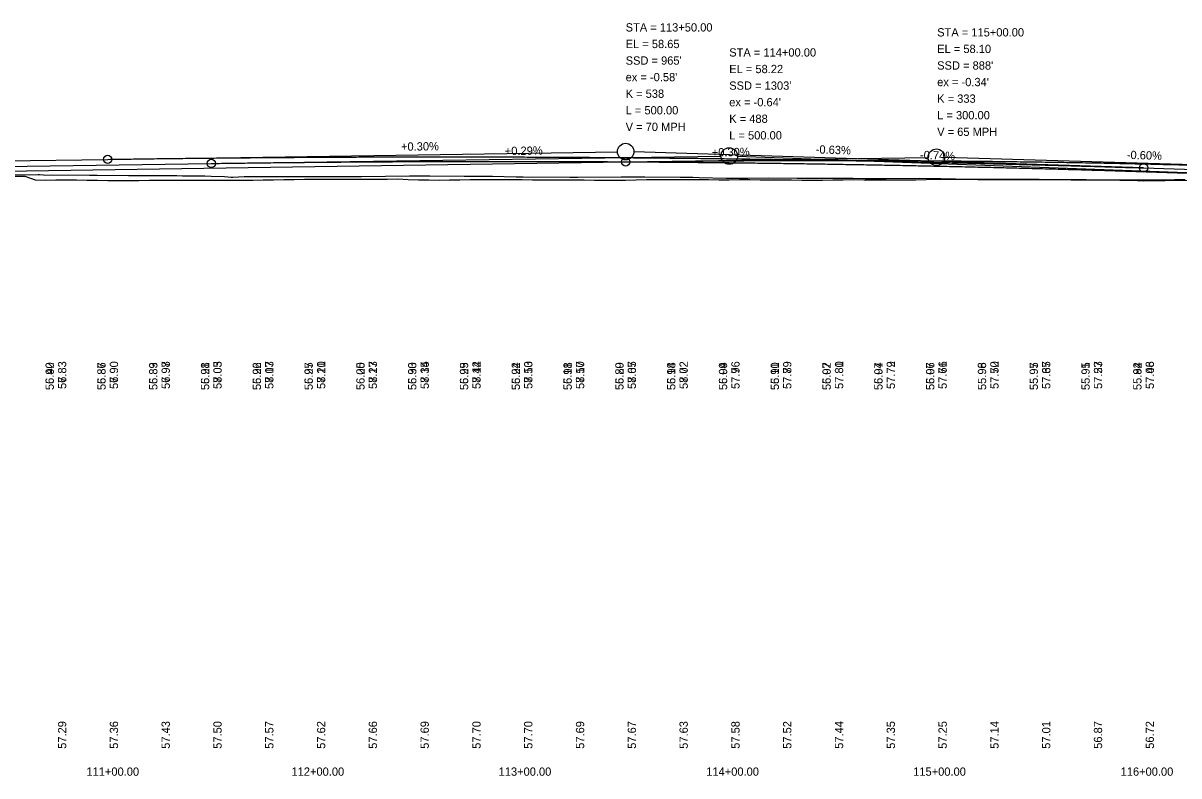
# Model space of a CAD drawing. Extents: x 3880794 to 3915434, y 287517 to 300173.
# Drawn here: x 3891597 to 3892155, y 296520 to 296883 of the extents above; entities that cross this region are included whole.
import ezdxf

# ---------------------------------------------------------------- set-up
doc = ezdxf.new("R2010")
doc.units = 0
for name, color, linetype in [('Level 1', 7, 'Continuous'), ('Level 2', 7, 'Continuous'), ('Level 30', 7, 'Continuous'), ('Level 31', 7, 'Continuous'), ('Level 32', 7, 'Continuous')]:
    doc.layers.add(name, color=color, linetype=linetype)

msp = doc.modelspace()

# ---------------------------------------------------------------- linework, layer by layer
at = {"layer": 'Level 1'}
for p, q in [((3891588.3, 296816.51), (3891638.3, 296817.26)), ((3891638.3, 296817.26), (3891884.3, 296820.95)), ((3891688.3, 296815.27), (3891934.3, 296818.8)), ((3892138.3, 296813.13), (3891892.3, 296820.88)), ((3892188.3, 296809.63), (3891942.29, 296818.71)), ((3891588.3, 296813.84), (3891688.3, 296815.27)), ((3892138.3, 296813.13), (3892188.3, 296811.56))]:
    msp.add_line(p, q, dxfattribs=at)
for points in [[(3891581.65, 296809.97), (3891600.37, 296809.86), (3891604.7, 296809.89), (3891605.35, 296809.88), (3891607.32, 296809.81), (3891629.58, 296809.63), (3891631.31, 296809.58), (3891633.14, 296809.55), (3891648.3, 296809.52), (3891649.99, 296809.48), (3891652.62, 296809.39), (3891671.74, 296809.39), (3891674.39, 296809.38), (3891685.2, 296809.27), (3891688.29, 296809.16), (3891694.76, 296808.97), (3891697.95, 296808.68), (3891698.68, 296808.69), (3891704.24, 296809.06), (3891705.15, 296809.06), (3891705.58, 296809.06), (3891712.33, 296809.05), (3891727.04, 296808.96), (3891728.62, 296808.94), (3891744.29, 296809.05), (3891752.67, 296809.04), (3891758.4, 296809.03), (3891760.76, 296809), (3891783.92, 296809.23), (3891784.67, 296809.23), (3891786.21, 296809.24), (3891793.8, 296809.27), (3891810.44, 296809.2), (3891810.78, 296809.19), (3891812.7, 296809.18), (3891813.11, 296809.18), (3891824.1, 296809.09), (3891835.39, 296808.87), (3891836.75, 296808.87), (3891838.85, 296808.87), (3891861.34, 296808.7), (3891862.59, 296808.69), (3891865.27, 296808.65), (3891886.15, 296808.77), (3891888.37, 296808.77), (3891894.43, 296808.76), (3891897.64, 296808.8), (3891914.61, 296808.65), (3891920.76, 296808.59), (3891923.81, 296808.56), (3891936.78, 296808.18), (3891947.35, 296808.19), (3891957.3, 296808.32), (3891971.1, 296808.16), (3891975.48, 296808.11), (3891981.2, 296808.1), (3891998.12, 296808.11), (3892003.94, 296808), (3892005.69, 296808), (3892013.98, 296808.09), (3892030.33, 296808.17), (3892040.44, 296808), (3892054.62, 296807.7), (3892056.89, 296807.65), (3892062.7, 296807.65), (3892078.69, 296807.69)], [(3892078.69, 296807.69), (3892086.3, 296807.63), (3892087.86, 296807.63), (3892094.52, 296807.59), (3892110.57, 296807.52), (3892118.26, 296807.44), (3892135.32, 296807.04), (3892138.13, 296806.96), (3892159.56, 296807.2)]]:
    msp.add_lwpolyline(points, dxfattribs=at)
for centre in [(3891888.3, 296821.01), (3891938.3, 296818.86)]:
    msp.add_circle(centre, 4, dxfattribs=at)
for points in [[(3891638.3, 296817.26), (3891648.3, 296817.4), (3891658.3, 296817.54), (3891668.3, 296817.67), (3891678.3, 296817.78), (3891688.3, 296817.89), (3891698.3, 296817.99), (3891708.3, 296818.08), (3891718.3, 296818.16), (3891728.3, 296818.23), (3891738.3, 296818.29), (3891748.3, 296818.34), (3891758.3, 296818.39), (3891768.3, 296818.42), (3891778.3, 296818.45), (3891788.3, 296818.46), (3891798.3, 296818.47), (3891808.3, 296818.46), (3891818.3, 296818.45), (3891828.3, 296818.43), (3891838.3, 296818.4), (3891848.3, 296818.36), (3891858.3, 296818.31), (3891868.3, 296818.25), (3891878.3, 296818.18), (3891888.3, 296818.1), (3891898.3, 296818.01), (3891908.3, 296817.92), (3891918.3, 296817.81), (3891928.3, 296817.7), (3891938.3, 296817.57), (3891948.3, 296817.44), (3891958.3, 296817.3), (3891968.3, 296817.14), (3891978.3, 296816.98), (3891988.3, 296816.81), (3891998.3, 296816.63), (3892008.3, 296816.44), (3892018.3, 296816.24), (3892028.3, 296816.03), (3892038.3, 296815.82), (3892048.3, 296815.59), (3892058.3, 296815.35), (3892068.3, 296815.11), (3892078.3, 296814.85), (3892088.3, 296814.59), (3892098.3, 296814.32), (3892108.3, 296814.04), (3892118.3, 296813.74), (3892128.3, 296813.44), (3892138.3, 296813.13)], [(3891688.3, 296815.27), (3891698.3, 296815.41), (3891708.3, 296815.54), (3891718.3, 296815.66), (3891728.3, 296815.77), (3891738.3, 296815.86), (3891748.3, 296815.95), (3891758.3, 296816.03), (3891768.3, 296816.09), (3891778.3, 296816.15), (3891788.3, 296816.19), (3891798.3, 296816.23), (3891808.3, 296816.26), (3891818.3, 296816.27), (3891828.3, 296816.28), (3891838.3, 296816.27), (3891848.3, 296816.26), (3891858.3, 296816.23), (3891868.3, 296816.19), (3891878.3, 296816.15), (3891888.3, 296816.09), (3891898.3, 296816.02), (3891908.3, 296815.95), (3891918.3, 296815.86), (3891928.3, 296815.76), (3891938.3, 296815.66), (3891948.3, 296815.54), (3891958.3, 296815.41), (3891968.3, 296815.27), (3891978.3, 296815.12), (3891988.3, 296814.96), (3891998.3, 296814.79), (3892008.3, 296814.62), (3892018.3, 296814.43), (3892028.3, 296814.23), (3892038.3, 296814.02), (3892048.3, 296813.8), (3892058.3, 296813.56), (3892068.3, 296813.32), (3892078.3, 296813.07), (3892088.3, 296812.81), (3892098.3, 296812.54), (3892108.3, 296812.26), (3892118.3, 296811.97), (3892128.3, 296811.66), (3892138.3, 296811.35), (3892148.3, 296811.03), (3892158.3, 296810.7), (3892168.3, 296810.35), (3892178.3, 296810), (3892188.3, 296809.63)]]:
    msp.add_spline(points, degree=3, dxfattribs=at)
at = {"layer": 'Level 2'}
for p, q in [((3891588.3, 296811.51), (3891888.3, 296816.01)), ((3891888.3, 296816.01), (3892034.3, 296818.2)), ((3892188.3, 296813.76), (3892042.3, 296818.14))]:
    msp.add_line(p, q, dxfattribs=at)
for points in [[(3891593.3, 296809.08), (3891598.3, 296809.2), (3891603.3, 296807.3), (3891608.3, 296807.29), (3891613.3, 296807.34), (3891618.3, 296807.36), (3891623.3, 296807.31), (3891628.3, 296807.25), (3891633.3, 296807.18), (3891638.3, 296807.1), (3891643.3, 296807.05), (3891648.3, 296807.08), (3891653.3, 296807.13), (3891658.3, 296807.18), (3891663.3, 296807.19), (3891668.3, 296807.2), (3891673.3, 296807.2), (3891678.3, 296807.19), (3891683.3, 296807.25), (3891688.3, 296807.29), (3891693.3, 296807.26), (3891698.3, 296807.23), (3891703.3, 296807.25), (3891708.3, 296807.26), (3891713.3, 296807.34), (3891718.3, 296807.4), (3891723.3, 296807.47), (3891728.3, 296807.55), (3891733.3, 296807.64), (3891738.3, 296807.63), (3891743.3, 296807.64), (3891748.3, 296807.7), (3891753.3, 296807.76), (3891758.3, 296807.75), (3891763.3, 296807.75), (3891768.3, 296807.67), (3891773.3, 296807.77), (3891778.3, 296807.78), (3891783.3, 296807.57), (3891788.3, 296807.39), (3891793.3, 296807.3), (3891798.3, 296807.23), (3891803.3, 296807.32), (3891808.3, 296807.43), (3891813.3, 296807.52), (3891818.3, 296807.52), (3891823.3, 296807.52), (3891828.3, 296807.5), (3891833.3, 296807.48), (3891838.3, 296807.46), (3891843.3, 296807.43), (3891848.3, 296807.39), (3891853.3, 296807.37), (3891858.3, 296807.36), (3891863.3, 296807.32), (3891868.3, 296807.3), (3891873.3, 296807.27), (3891878.3, 296807.24), (3891883.3, 296807.19), (3891888.3, 296807.21), (3891893.3, 296807.34), (3891898.3, 296807.46), (3891903.3, 296807.49), (3891908.3, 296807.48), (3891913.3, 296807.48), (3891918.3, 296807.53), (3891923.3, 296807.58), (3891928.3, 296807.5), (3891933.3, 296807.41), (3891938.3, 296807.43), (3891943.3, 296807.49), (3891948.3, 296807.46), (3891953.3, 296807.39), (3891958.3, 296807.32), (3891963.3, 296807.31), (3891968.3, 296807.31), (3891973.3, 296807.29), (3891978.3, 296807.25), (3891983.3, 296807.24), (3891988.3, 296807.35), (3891993.3, 296807.45), (3891998.3, 296807.48), (3892003.3, 296807.43), (3892008.3, 296807.43), (3892013.3, 296807.44), (3892018.3, 296807.45), (3892023.3, 296807.44), (3892028.3, 296807.43), (3892033.3, 296807.48), (3892038.3, 296807.62)], [(3892038.3, 296807.62), (3892043.3, 296807.75), (3892048.3, 296807.76), (3892053.3, 296807.68), (3892058.3, 296807.59), (3892063.3, 296807.55), (3892068.3, 296807.53), (3892073.3, 296807.51), (3892078.3, 296807.48), (3892083.3, 296807.48), (3892088.3, 296807.53), (3892093.3, 296807.58), (3892098.3, 296807.49), (3892103.3, 296807.37), (3892108.3, 296807.33), (3892113.3, 296807.33), (3892118.3, 296807.33), (3892123.3, 296807.32), (3892128.3, 296807.31), (3892133.3, 296807.34), (3892138.3, 296807.38), (3892143.3, 296807.42), (3892148.3, 296807.45), (3892153.3, 296807.47), (3892158.3, 296807.46)]]:
    msp.add_lwpolyline(points, dxfattribs=at)
for centre, radius in [((3892038.3, 296818.26), 4), ((3891888.3, 296816.01), 2)]:
    msp.add_circle(centre, radius, dxfattribs=at)
msp.add_spline([(3891888.3, 296816.01), (3891894.3, 296816.09), (3891900.3, 296816.18), (3891906.3, 296816.25), (3891912.3, 296816.32), (3891918.3, 296816.39), (3891924.3, 296816.45), (3891930.3, 296816.5), (3891936.3, 296816.55), (3891942.3, 296816.6), (3891948.3, 296816.64), (3891954.3, 296816.67), (3891960.3, 296816.7), (3891966.3, 296816.72), (3891972.3, 296816.74), (3891978.3, 296816.75), (3891984.3, 296816.76), (3891990.3, 296816.76), (3891996.3, 296816.75), (3892002.3, 296816.74), (3892008.3, 296816.73), (3892014.3, 296816.71), (3892020.3, 296816.68), (3892026.3, 296816.65), (3892032.3, 296816.61), (3892038.3, 296816.57), (3892044.3, 296816.52), (3892050.3, 296816.47), (3892056.3, 296816.41), (3892062.3, 296816.35), (3892068.3, 296816.28), (3892074.3, 296816.2), (3892080.3, 296816.12), (3892086.3, 296816.04), (3892092.3, 296815.95), (3892098.3, 296815.85), (3892104.3, 296815.75), (3892110.3, 296815.64), (3892116.3, 296815.53), (3892122.3, 296815.41), (3892128.3, 296815.29), (3892134.3, 296815.16), (3892140.3, 296815.02), (3892146.3, 296814.88), (3892152.3, 296814.74), (3892158.3, 296814.59), (3892164.3, 296814.43), (3892170.3, 296814.27), (3892176.3, 296814.11), (3892182.3, 296813.93), (3892188.3, 296813.76)], degree=3, dxfattribs=at)
at = {"layer": 'Level 31'}
for centre in [(3891638.3, 296817.26), (3891688.3, 296815.27), (3892138.3, 296813.13)]:
    msp.add_circle(centre, 2, dxfattribs=at)

# ---------------------------------------------------------------- texts
at = {"layer": 'Level 2'}
for s, p in [('STA = 115+00.00', (3892038.67, 296876.57)), ('EL = 58.10', (3892038.67, 296868.57)), ("SSD = 888'", (3892038.67, 296860.57)), ("ex = -0.34'", (3892038.67, 296852.57)), ('K = 333', (3892038.67, 296844.57)), ('L = 300.00', (3892038.67, 296836.57)), ('V = 65 MPH', (3892038.67, 296828.57)), ('111+00.00', (3891628.03, 296519.76)), ('112+00.00', (3891727.02, 296519.76)), ('113+00.00', (3891826.99, 296519.76)), ('114+00.00', (3891927.21, 296519.76)), ('115+00.00', (3892027.09, 296519.76)), ('116+00.00', (3892127.21, 296519.76))]:
    msp.add_text(s, height=4, dxfattribs=at).set_placement(p)
for s, rotation, p in [('+0.30%', 0.8594, (3891929.9, 296818.63)), ('-0.60%', 358.2816, (3892130.16, 296817.5)), ('56.83', 90, (3891618.3, 296706.43)), ('56.90', 90, (3891643.3, 296706.43)), ('56.98', 90, (3891668.3, 296706.43)), ('57.05', 90, (3891693.3, 296706.43)), ('57.13', 90, (3891718.3, 296706.43)), ('57.20', 90, (3891743.3, 296706.43)), ('57.27', 90, (3891768.3, 296706.43)), ('57.35', 90, (3891793.3, 296706.43)), ('57.42', 90, (3891818.3, 296706.43)), ('57.50', 90, (3891843.3, 296706.43)), ('57.57', 90, (3891868.3, 296706.43)), ('57.65', 90, (3891893.3, 296706.43)), ('57.72', 90, (3891918.3, 296706.43)), ('57.76', 90, (3891943.3, 296706.43)), ('57.79', 90, (3891968.3, 296706.43)), ('57.80', 90, (3891993.3, 296706.43)), ('57.79', 90, (3892018.3, 296706.43)), ('57.76', 90, (3892043.3, 296706.43)), ('57.72', 90, (3892068.3, 296706.43)), ('57.65', 90, (3892093.3, 296706.43)), ('57.57', 90, (3892118.3, 296706.43)), ('57.46', 90, (3892143.3, 296706.43))]:
    msp.add_text(s, height=4, rotation=rotation, dxfattribs=at).set_placement(p)
at = {"layer": 'Level 30'}
for s, p in [('56.40', (3891612.3, 296705.91)), ('56.36', (3891637.3, 296705.91)), ('56.33', (3891662.3, 296705.91)), ('56.28', (3891687.3, 296705.91)), ('56.26', (3891712.3, 296705.91)), ('56.25', (3891737.3, 296705.91)), ('56.25', (3891762.3, 296705.91)), ('56.30', (3891787.3, 296705.91)), ('56.29', (3891812.3, 296705.91)), ('56.22', (3891837.3, 296705.91)), ('56.18', (3891862.3, 296705.91)), ('56.20', (3891887.3, 296705.91)), ('56.18', (3891912.3, 296705.91)), ('56.09', (3891937.3, 296705.91)), ('56.10', (3891962.3, 296705.91)), ('56.07', (3891987.3, 296705.91)), ('56.07', (3892012.3, 296705.91)), ('56.06', (3892037.3, 296705.91)), ('55.98', (3892062.3, 296705.91)), ('55.97', (3892087.3, 296705.91)), ('55.95', (3892112.3, 296705.91)), ('55.84', (3892137.3, 296705.91))]:
    msp.add_text(s, height=4, rotation=90, dxfattribs=at).set_placement(p)
for s, p in [('111+00.00', (3891628.03, 296519.76)), ('111+00.00', (3891628.03, 296519.76)), ('111+00.00', (3891628.03, 296519.76)), ('112+00.00', (3891727.02, 296519.76)), ('112+00.00', (3891727.02, 296519.76)), ('112+00.00', (3891727.02, 296519.76)), ('113+00.00', (3891826.99, 296519.76)), ('113+00.00', (3891826.99, 296519.76)), ('113+00.00', (3891826.99, 296519.76)), ('114+00.00', (3891927.21, 296519.76)), ('114+00.00', (3891927.21, 296519.76)), ('114+00.00', (3891927.21, 296519.76)), ('115+00.00', (3892027.09, 296519.76)), ('115+00.00', (3892027.09, 296519.76)), ('115+00.00', (3892027.09, 296519.76)), ('116+00.00', (3892127.21, 296519.76)), ('116+00.00', (3892127.21, 296519.76)), ('116+00.00', (3892127.21, 296519.76))]:
    msp.add_text(s, height=4, dxfattribs=at).set_placement(p)
at = {"layer": 'Level 31'}
for s, p in [('STA = 113+50.00', (3891888.3, 296878.95)), ('EL = 58.65', (3891888.3, 296870.95)), ("SSD = 965'", (3891888.3, 296862.95)), ('STA = 114+00.00', (3891938.3, 296866.86)), ('EL = 58.22', (3891938.3, 296858.86)), ("ex = -0.58'", (3891888.3, 296854.95)), ("SSD = 1303'", (3891938.3, 296850.86)), ('K = 538', (3891888.3, 296846.95)), ("ex = -0.64'", (3891938.3, 296842.86)), ('L = 500.00', (3891888.3, 296838.95)), ('K = 488', (3891938.3, 296834.86)), ('V = 70 MPH', (3891888.3, 296830.95)), ('L = 500.00', (3891938.3, 296826.86))]:
    msp.add_text(s, height=4, dxfattribs=at).set_placement(p)
for s, rotation, p in [('+0.30%', 0.8594, (3891779.9, 296821.38)), ('+0.29%', 0.8212, (3891830, 296819.3)), ('-0.63%', 358.1958, (3891980, 296820.12)), ('-0.74%', 357.8874, (3892030.31, 296817.47)), ('57.83', 90, (3891618.3, 296706.43)), ('57.90', 90, (3891643.3, 296706.43)), ('57.97', 90, (3891668.3, 296706.43)), ('58.03', 90, (3891693.3, 296706.43)), ('58.07', 90, (3891718.3, 296706.43)), ('58.11', 90, (3891743.3, 296706.43)), ('58.13', 90, (3891768.3, 296706.43)), ('58.14', 90, (3891793.3, 296706.43)), ('58.14', 90, (3891818.3, 296706.43)), ('58.13', 90, (3891843.3, 296706.43)), ('58.10', 90, (3891868.3, 296706.43)), ('58.07', 90, (3891893.3, 296706.43)), ('58.02', 90, (3891918.3, 296706.43)), ('57.96', 90, (3891943.3, 296706.43)), ('57.89', 90, (3891968.3, 296706.43)), ('57.81', 90, (3891993.3, 296706.43)), ('57.72', 90, (3892018.3, 296706.43)), ('57.61', 90, (3892043.3, 296706.43)), ('57.50', 90, (3892068.3, 296706.43)), ('57.37', 90, (3892093.3, 296706.43)), ('57.23', 90, (3892118.3, 296706.43)), ('57.08', 90, (3892143.3, 296706.43)), ('57.29', 90, (3891618.3, 296532.76)), ('57.36', 90, (3891643.3, 296532.76)), ('57.43', 90, (3891668.3, 296532.76)), ('57.50', 90, (3891693.3, 296532.76)), ('57.57', 90, (3891718.3, 296532.76)), ('57.62', 90, (3891743.3, 296532.76)), ('57.66', 90, (3891768.3, 296532.76)), ('57.69', 90, (3891793.3, 296532.76)), ('57.70', 90, (3891818.3, 296532.76)), ('57.70', 90, (3891843.3, 296532.76)), ('57.69', 90, (3891868.3, 296532.76)), ('57.67', 90, (3891893.3, 296532.76)), ('57.63', 90, (3891918.3, 296532.76)), ('57.58', 90, (3891943.3, 296532.76)), ('57.52', 90, (3891968.3, 296532.76)), ('57.44', 90, (3891993.3, 296532.76)), ('57.35', 90, (3892018.3, 296532.76)), ('57.25', 90, (3892043.3, 296532.76)), ('57.14', 90, (3892068.3, 296532.76)), ('57.01', 90, (3892093.3, 296532.76)), ('56.87', 90, (3892118.3, 296532.76)), ('56.72', 90, (3892143.3, 296532.76))]:
    msp.add_text(s, height=4, rotation=rotation, dxfattribs=at).set_placement(p)
at = {"layer": 'Level 32'}
for s, p in [('55.92', (3891612.3, 296705.91)), ('55.87', (3891637.3, 296705.91)), ('55.89', (3891662.3, 296705.91)), ('55.91', (3891687.3, 296705.91)), ('55.92', (3891712.3, 296705.91)), ('55.97', (3891737.3, 296705.91)), ('56.00', (3891762.3, 296705.91)), ('55.93', (3891787.3, 296705.91)), ('55.95', (3891812.3, 296705.91)), ('55.94', (3891837.3, 296705.91)), ('55.91', (3891862.3, 296705.91)), ('55.89', (3891887.3, 296705.91)), ('55.94', (3891912.3, 296705.91)), ('55.94', (3891937.3, 296705.91)), ('55.91', (3891962.3, 296705.91)), ('55.92', (3891987.3, 296705.91)), ('55.94', (3892012.3, 296705.91)), ('55.97', (3892037.3, 296705.91)), ('55.96', (3892062.3, 296705.91)), ('55.95', (3892087.3, 296705.91)), ('55.91', (3892112.3, 296705.91)), ('55.92', (3892137.3, 296705.91))]:
    msp.add_text(s, height=4, rotation=90, dxfattribs=at).set_placement(p)

doc.saveas('drawing.dxf')
